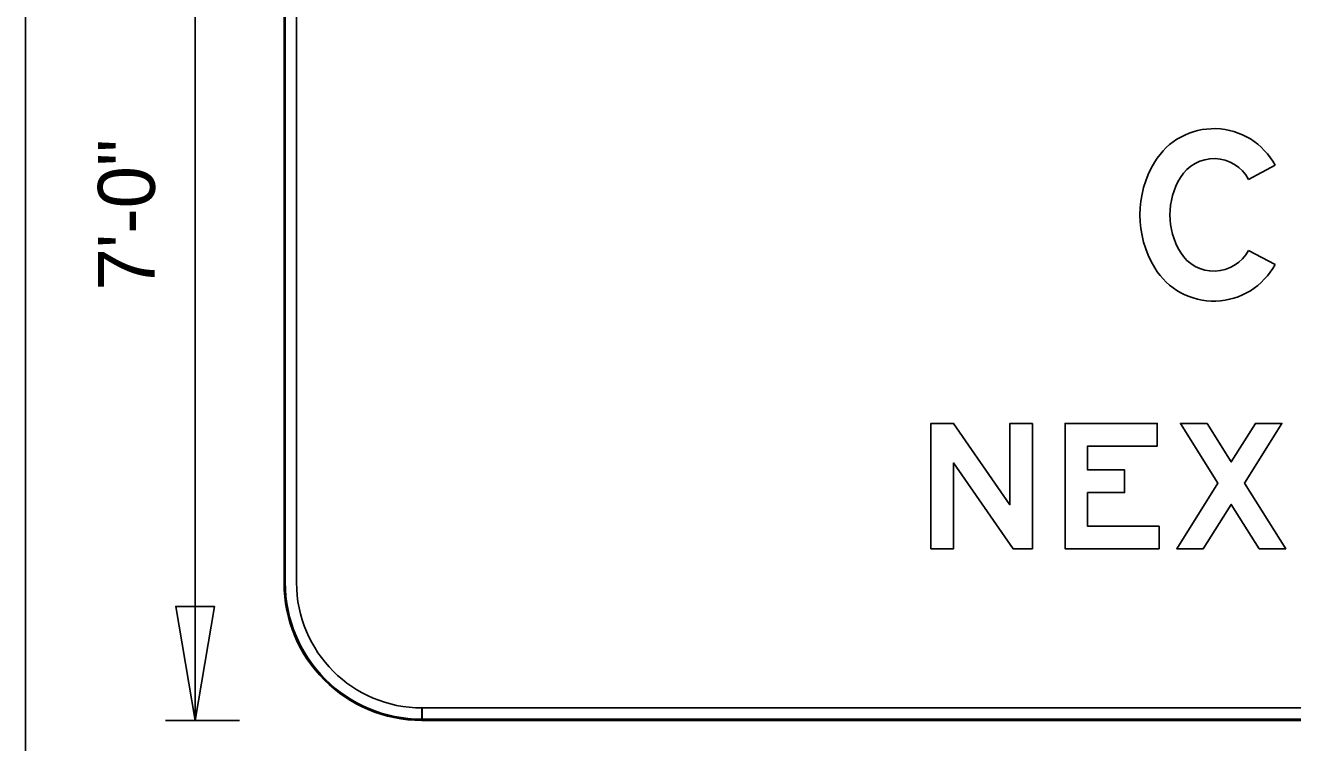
# Model space of a CAD drawing. Extents: x 0 to 770, y 0 to 495.
# Drawn here: x 577.5 to 655.4, y 401.2 to 445.3 of the extents above; entities that cross this region are included whole.
import ezdxf

# ---------------------------------------------------------------- set-up
doc = ezdxf.new("R2010")
doc.units = 0
for name, color, linetype in [('Default', 7, 'Continuous'), ('Dimension', 7, 'Continuous'), ('GSBWFill', 7, 'Continuous'), ('GSColorFill', 7, 'Continuous'), ('GSDims', 7, 'Continuous'), ('GSOutline', 7, 'Continuous'), ('SheetLines_dp', 7, 'Continuous')]:
    doc.layers.add(name, color=color, linetype=linetype)

msp = doc.modelspace()

# ---------------------------------------------------------------- linework, layer by layer
at = {"layer": 'Dimension'}
msp.add_lwpolyline([(587.942, 402.575), (589.13, 409.591), (586.753, 409.591)], close=True, dxfattribs=at)
at = {"layer": 'GSBWFill'}
for p, q in [((593.406, 458.853), (593.406, 411.055)), ((593.406, 458.853), (593.406, 411.055)), ((594.177, 411.055), (594.177, 458.853)), ((652.713, 435.865), (654.342, 436.732)), ((654.342, 430.631), (652.713, 431.499)), ((652.713, 431.499), (652.713, 431.499)), ((601.886, 402.575), (601.886, 403.346)), ((732.944, 403.346), (601.894, 403.346)), ((601.894, 403.346), (601.894, 402.575)), ((601.886, 402.575), (732.944, 402.575)), ((601.894, 402.575), (732.944, 402.575))]:
    msp.add_line(p, q, dxfattribs=at)
for points in [[(639.43, 420.846), (639.43, 413.136), (638.235, 413.136), (634.574, 418.417), (634.574, 413.136), (633.186, 413.136), (633.186, 420.846), (634.578, 420.846), (638.043, 415.85), (638.043, 420.846)], [(647.217, 414.524), (642.822, 414.524), (642.822, 416.598), (645.097, 416.598), (645.097, 417.985), (642.822, 417.985), (642.822, 419.458), (647.101, 419.458), (647.101, 420.846), (641.435, 420.846), (641.435, 413.136), (647.217, 413.136)], [(653.365, 413.136), (651.65, 415.87), (649.934, 413.136), (648.296, 413.136), (650.831, 417.175), (648.527, 420.846), (650.166, 420.846), (651.65, 418.481), (653.134, 420.846), (654.772, 420.846), (652.469, 417.175), (655.003, 413.136)]]:
    msp.add_lwpolyline(points, close=True, dxfattribs=at)
for centre, radius, start, end in [((650.586, 434.733), 4.255, 28.02648, 148.74991), ((652.318, 433.682), 6.281, 148.74991, 211.25009), ((650.586, 434.733), 2.41, 28.02648, 148.74991), ((652.318, 433.682), 4.435, 148.74991, 211.25009), ((650.586, 432.631), 2.41, 211.25009, 331.97353), ((650.586, 432.631), 4.255, 211.25009, 331.97352), ((601.886, 411.055), 8.48, 180, 270), ((601.886, 411.055), 8.48, 180, 270), ((601.886, 411.055), 7.709, 180, 270)]:
    msp.add_arc(centre, radius, start, end, dxfattribs=at)
at = {"layer": 'GSColorFill'}
for p, q in [((593.406, 458.853), (593.406, 411.055)), ((593.406, 458.853), (593.406, 411.055)), ((593.406, 458.853), (593.406, 411.055)), ((593.483, 411.055), (593.483, 458.853)), ((594.177, 411.055), (594.177, 458.853)), ((652.713, 435.865), (654.342, 436.732)), ((654.342, 430.631), (652.713, 431.499)), ((652.713, 431.499), (652.713, 431.499)), ((601.886, 402.575), (601.886, 403.346)), ((732.944, 403.346), (601.894, 403.346)), ((601.894, 403.346), (601.894, 402.575)), ((601.886, 402.575), (601.886, 402.652)), ((601.886, 402.575), (732.944, 402.575)), ((732.944, 402.652), (601.887, 402.652)), ((601.887, 402.652), (601.887, 402.575)), ((601.887, 402.575), (732.944, 402.575)), ((601.894, 402.575), (732.944, 402.575))]:
    msp.add_line(p, q, dxfattribs=at)
for points in [[(639.43, 420.846), (639.43, 413.136), (638.235, 413.136), (634.574, 418.417), (634.574, 413.136), (633.186, 413.136), (633.186, 420.846), (634.578, 420.846), (638.043, 415.85), (638.043, 420.846)], [(647.217, 414.524), (642.822, 414.524), (642.822, 416.598), (645.097, 416.598), (645.097, 417.985), (642.822, 417.985), (642.822, 419.458), (647.101, 419.458), (647.101, 420.846), (641.435, 420.846), (641.435, 413.136), (647.217, 413.136)], [(653.365, 413.136), (651.65, 415.87), (649.934, 413.136), (648.296, 413.136), (650.831, 417.175), (648.527, 420.846), (650.166, 420.846), (651.65, 418.481), (653.134, 420.846), (654.772, 420.846), (652.469, 417.175), (655.003, 413.136)]]:
    msp.add_lwpolyline(points, close=True, dxfattribs=at)
for centre, radius, start, end in [((650.586, 434.733), 4.255, 28.02648, 148.74991), ((652.318, 433.682), 6.281, 148.74991, 211.25009), ((650.586, 434.733), 2.41, 28.02648, 148.74991), ((652.318, 433.682), 4.435, 148.74991, 211.25009), ((650.586, 432.631), 2.41, 211.25009, 331.97353), ((650.586, 432.631), 4.255, 211.25009, 331.97352), ((601.886, 411.055), 8.48, 180, 270), ((601.886, 411.055), 8.48, 180, 270), ((601.886, 411.055), 8.48, 180, 270), ((601.886, 411.055), 8.403, 180, 270), ((601.886, 411.055), 7.709, 180, 270)]:
    msp.add_arc(centre, radius, start, end, dxfattribs=at)
at = {"layer": 'GSDims'}
for p, q in [((587.942, 402.575), (587.942, 467.333)), ((590.674, 402.575), (586.12, 402.575))]:
    msp.add_line(p, q, dxfattribs=at)
at = {"layer": 'GSOutline'}
for p, q in [((593.406, 458.853), (593.406, 411.055)), ((593.406, 458.853), (593.406, 411.055)), ((594.177, 458.853), (594.177, 411.055)), ((652.713, 435.865), (654.342, 436.732)), ((654.342, 430.631), (652.713, 431.499)), ((652.713, 431.499), (652.713, 431.499)), ((601.886, 403.346), (732.944, 403.346)), ((601.886, 402.575), (732.944, 402.575)), ((601.886, 402.575), (732.944, 402.575))]:
    msp.add_line(p, q, dxfattribs=at)
for points in [[(639.43, 420.846), (639.43, 413.136), (638.235, 413.136), (634.574, 418.417), (634.574, 413.136), (633.186, 413.136), (633.186, 420.846), (634.578, 420.846), (638.043, 415.85), (638.043, 420.846)], [(647.217, 414.524), (642.822, 414.524), (642.822, 416.598), (645.097, 416.598), (645.097, 417.985), (642.822, 417.985), (642.822, 419.458), (647.101, 419.458), (647.101, 420.846), (641.435, 420.846), (641.435, 413.136), (647.217, 413.136)], [(653.365, 413.136), (651.65, 415.87), (649.934, 413.136), (648.296, 413.136), (650.831, 417.175), (648.527, 420.846), (650.166, 420.846), (651.65, 418.481), (653.134, 420.846), (654.772, 420.846), (652.469, 417.175), (655.003, 413.136)]]:
    msp.add_lwpolyline(points, close=True, dxfattribs=at)
for centre, radius, start, end in [((650.586, 434.733), 4.255, 28.02648, 148.74991), ((652.318, 433.682), 6.281, 148.74991, 211.25009), ((650.586, 434.733), 2.41, 28.02648, 148.74991), ((652.318, 433.682), 4.435, 148.74991, 211.25009), ((650.586, 432.631), 2.41, 211.25009, 331.97353), ((650.586, 432.631), 4.255, 211.25009, 331.97352), ((601.886, 411.055), 8.48, 180, 270), ((601.886, 411.055), 8.48, 180, 270), ((601.886, 411.055), 7.709, 180, 270)]:
    msp.add_arc(centre, radius, start, end, dxfattribs=at)
at = {"layer": 'SheetLines_dp'}
msp.add_line((577.501, 330), (577.501, 495), dxfattribs=at)

# ---------------------------------------------------------------- texts
at = {"layer": 'Default'}
msp.add_text('7\'-0"', height=3.5, rotation=90, dxfattribs=at).set_placement((585.462, 429.025))

doc.saveas('drawing.dxf')
